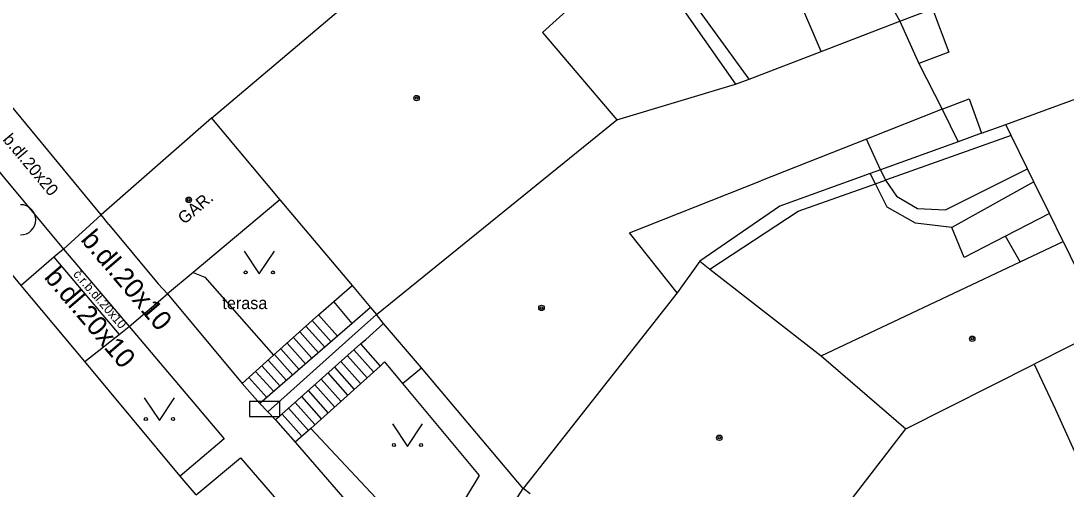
# Model space of a CAD drawing. Extents: x -595546 to -593986, y -1160845 to -1159202.
# Drawn here: x -595188.46 to -595153.91, y -1160596.94 to -1160581.47 of the extents above; entities that cross this region are included whole.
import ezdxf

# ---------------------------------------------------------------- set-up
doc = ezdxf.new("R2010")
doc.units = 0
for name, color, linetype in [('DOP - kresba z DSPS bez souradnic', 7, 'Continuous'), ('DOP - rozhrani ploch obecne', 7, 'Continuous'), ('Level 22', 7, 'Continuous'), ('Level 24', 7, 'Continuous'), ('Level 36', 7, 'Continuous'), ('Level 39', 7, 'Continuous'), ('TM - budovy zdene_ betonove - VP', 7, 'Continuous'), ('TM - chodniky - VP', 7, 'Continuous'), ('TM - komunikace - VP', 7, 'Continuous'), ('TM - letecke snimky - pomocna linie', 7, 'Continuous'), ('TM - podezdivka plotu - VP', 7, 'Continuous'), ('TM - popis objektu', 7, 'Continuous'), ('TM - popis povrchu', 7, 'Continuous'), ('TM - poznamka', 7, 'Continuous'), ('TM - rozhrani mezi zpev. plochami mezi sebou - VP', 7, 'Continuous'), ('TM - rozhrani ploch obecne - VP', 7, 'Continuous'), ('TM - schody - VP', 7, 'Continuous'), ('TM - vstup do budovy - zdene_ betonove', 7, 'Continuous'), ('TM - zed operna - VP', 7, 'Continuous')]:
    doc.layers.add(name, color=color, linetype=linetype)

msp = doc.modelspace()

# ---------------------------------------------------------------- linework, layer by layer
at = {"layer": 'DOP - kresba z DSPS bez souradnic'}
for points in [[(-595164.38, -1160583.39), (-595169.19, -1160576.78)], [(-595158, -1160584.39), (-595157.48, -1160585.46)], [(-595160.04, -1160586.39), (-595160.51, -1160585.38)], [(-595155.72, -1160585.26), (-595159.88, -1160586.73)], [(-595160.04, -1160586.39), (-595159.88, -1160586.73)], [(-595157.9, -1160587.71), (-595155.18, -1160586.36)], [(-595160.21, -1160586.85), (-595160.38, -1160586.51)], [(-595159.88, -1160586.73), (-595159.52, -1160587.26)], [(-595162.76, -1160587.75), (-595160.21, -1160586.85)], [(-595159.82, -1160587.62), (-595160.21, -1160586.85)], [(-595154.97, -1160586.79), (-595157.68, -1160588.29)], [(-595159.52, -1160587.26), (-595158.82, -1160587.67)], [(-595165.69, -1160589.67), (-595162.76, -1160587.75)], [(-595158.89, -1160588.15), (-595159.82, -1160587.62)], [(-595158.82, -1160587.67), (-595157.9, -1160587.71)], [(-595157.68, -1160588.29), (-595158.89, -1160588.15)], [(-595154.46, -1160587.83), (-595155.91, -1160588.58)], [(-595157.28, -1160589.29), (-595157.68, -1160588.29)], [(-595155.91, -1160588.58), (-595157.28, -1160589.29)], [(-595155.43, -1160589.43), (-595155.91, -1160588.58)]]:
    msp.add_lwpolyline(points, dxfattribs=at)
at = {"layer": 'DOP - rozhrani ploch obecne'}
for points in [[(-595169.65, -1160576.69), (-595164.84, -1160583.56)], [(-595159.4, -1160581.48), (-595158.33, -1160581.07)], [(-595158.33, -1160581.07), (-595157.78, -1160582.5)], [(-595157.78, -1160582.5), (-595158.78, -1160582.88)], [(-595155.9, -1160584.89), (-595152.8, -1160583.76)], [(-595158, -1160584.39), (-595157.11, -1160584.04)], [(-595157.11, -1160584.04), (-595156.7, -1160585.18)], [(-595156.7, -1160585.18), (-595155.9, -1160584.89)], [(-595155.72, -1160585.26), (-595155.9, -1160584.89)], [(-595156.7, -1160585.18), (-595157.48, -1160585.46)], [(-595155.18, -1160586.36), (-595155.72, -1160585.26)], [(-595157.48, -1160585.46), (-595160.04, -1160586.39)], [(-595160.04, -1160586.39), (-595160.38, -1160586.51)], [(-595154.97, -1160586.79), (-595155.18, -1160586.36)], [(-595160.38, -1160586.51), (-595163.37, -1160587.59)], [(-595154.46, -1160587.83), (-595154.97, -1160586.79)], [(-595163.37, -1160587.59), (-595166.02, -1160589.41)], [(-595154.01, -1160588.76), (-595154.46, -1160587.83)]]:
    msp.add_lwpolyline(points, dxfattribs=at)
at = {"layer": 'Level 22'}
msp.add_arc((-595188.47, -1160588.04), 0.5, 270, 90, dxfattribs=at)
at = {"layer": 'Level 24'}
msp.add_lwpolyline([(-595180.898, -1160594.539), (-595179.898, -1160594.539), (-595179.898, -1160594.039), (-595180.898, -1160594.039)], close=True, dxfattribs=at)
at = {"layer": 'Level 36'}
for points in [[(-595181.08, -1160589.08), (-595180.58, -1160589.83), (-595180.08, -1160589.08)], [(-595184.38, -1160593.92), (-595183.88, -1160594.67), (-595183.38, -1160593.92)], [(-595176.18, -1160594.78), (-595175.68, -1160595.53), (-595175.18, -1160594.78)]]:
    msp.add_lwpolyline(points, dxfattribs=at)
for centre in [(-595181.03, -1160589.78), (-595180.131, -1160589.78), (-595184.33, -1160594.62), (-595183.431, -1160594.62), (-595176.13, -1160595.48), (-595175.231, -1160595.48)]:
    msp.add_circle(centre, 0.05, dxfattribs=at)
at = {"layer": 'Level 39'}
for centre, radius in [((-595175.38, -1160584.02), 0.09), ((-595175.38, -1160584.02), 0.0398), ((-595182.91, -1160587.38), 0.09), ((-595182.91, -1160587.38), 0.0398), ((-595171.25, -1160590.95), 0.09), ((-595171.25, -1160590.95), 0.0398), ((-595157.01, -1160591.97), 0.09), ((-595157.01, -1160591.97), 0.0398), ((-595165.37, -1160595.24), 0.09), ((-595165.37, -1160595.24), 0.0398)]:
    msp.add_circle(centre, radius, dxfattribs=at)
at = {"layer": 'TM - budovy zdene_ betonove - VP'}
for points in [[(-595162, -1160582.48), (-595163.68, -1160578.57)], [(-595182.16, -1160584.68), (-595175.26, -1160578.85)], [(-595169.86, -1160580.62), (-595171.22, -1160581.85)], [(-595159.57, -1160581.18), (-595159.4, -1160581.48)], [(-595162, -1160582.48), (-595159.4, -1160581.48)], [(-595159.4, -1160581.48), (-595158.78, -1160582.88)], [(-595171.22, -1160581.85), (-595168.76, -1160584.74)], [(-595164.38, -1160583.39), (-595162, -1160582.48)], [(-595158.78, -1160582.88), (-595158, -1160584.39)], [(-595185.81, -1160587.88), (-595189.71, -1160583.16)], [(-595168.76, -1160584.74), (-595164.84, -1160583.56)], [(-595164.84, -1160583.56), (-595164.38, -1160583.39)], [(-595182.16, -1160584.68), (-595185.81, -1160587.88)], [(-595182.16, -1160584.68), (-595179.9, -1160587.38)], [(-595158, -1160584.39), (-595160.51, -1160585.38)], [(-595176.71, -1160591.17), (-595168.76, -1160584.74)], [(-595160.51, -1160585.38), (-595164, -1160586.75)], [(-595168.34, -1160588.47), (-595164, -1160586.75)], [(-595179.9, -1160587.38), (-595182.77, -1160589.78)], [(-595179.9, -1160587.38), (-595177.51, -1160590.21)], [(-595185.55, -1160588.2), (-595185.81, -1160587.88)], [(-595166.77, -1160590.45), (-595168.34, -1160588.47)], [(-595155.43, -1160589.43), (-595154.01, -1160588.76)], [(-595154.01, -1160588.76), (-595152.61, -1160591.62)], [(-595166.02, -1160589.41), (-595166.77, -1160590.45)], [(-595166.02, -1160589.41), (-595165.69, -1160589.67)], [(-595162, -1160592.53), (-595155.43, -1160589.43)], [(-595182.77, -1160589.78), (-595183.61, -1160590.48)], [(-595165.69, -1160589.67), (-595162, -1160592.53)], [(-595183.61, -1160590.48), (-595183.92, -1160590.16)], [(-595177.51, -1160590.21), (-595176.9, -1160590.94)], [(-595166.77, -1160590.45), (-595171.86, -1160596.92)], [(-595176.9, -1160590.94), (-595176.71, -1160591.17)], [(-595176.47, -1160591.46), (-595176.71, -1160591.17)], [(-595175.22, -1160592.93), (-595176.47, -1160591.46)], [(-595152.61, -1160591.62), (-595154.96, -1160592.81)], [(-595162, -1160592.53), (-595159.21, -1160594.95)], [(-595171.86, -1160596.92), (-595175.22, -1160592.93)], [(-595159.21, -1160594.95), (-595154.96, -1160592.81)], [(-595154.96, -1160592.81), (-595154.26, -1160594.31)], [(-595154.26, -1160594.31), (-595153.43, -1160596.13)], [(-595164.68, -1160602.05), (-595159.21, -1160594.95)], [(-595171.62, -1160597.09), (-595171.86, -1160596.92)]]:
    msp.add_lwpolyline(points, dxfattribs=at)
at = {"layer": 'TM - chodniky - VP'}
for points in [[(-595191.02, -1160584.25), (-595187.05, -1160589.01)], [(-595187.05, -1160589.01), (-595187.37, -1160589.27)], [(-595187.37, -1160589.27), (-595188.45, -1160590.21)], [(-595178.12, -1160590.74), (-595177.51, -1160590.21)], [(-595178.62, -1160591.18), (-595178.12, -1160590.74)], [(-595185.21, -1160591.83), (-595184.88, -1160591.56)], [(-595184.88, -1160591.56), (-595181.74, -1160595.28)], [(-595186.35, -1160592.72), (-595185.21, -1160591.83)], [(-595176.58, -1160592.87), (-595176.44, -1160592.73)], [(-595176.44, -1160592.73), (-595175.84, -1160593.45)], [(-595175.84, -1160593.45), (-595175.22, -1160592.93)], [(-595181.74, -1160595.28), (-595183.19, -1160596.51)], [(-595182.67, -1160597.12), (-595181.2, -1160595.9)], [(-595181.2, -1160595.9), (-595177.29, -1160600.43)]]:
    msp.add_lwpolyline(points, dxfattribs=at)
at = {"layer": 'TM - komunikace - VP'}
for points in [[(-595188.45, -1160590.21), (-595189.58, -1160588.86)], [(-595186.35, -1160592.72), (-595188.45, -1160590.21)], [(-595183.19, -1160596.51), (-595186.35, -1160592.72)], [(-595182.67, -1160597.12), (-595183.19, -1160596.51)]]:
    msp.add_lwpolyline(points, dxfattribs=at)
at = {"layer": 'TM - letecke snimky - pomocna linie'}
for points in [[(-595160.21, -1160586.85), (-595159.88, -1160586.73)], [(-595175.84, -1160593.45), (-595173.31, -1160596.49), (-595174.92, -1160599.15)]]:
    msp.add_lwpolyline(points, dxfattribs=at)
at = {"layer": 'TM - podezdivka plotu - VP'}
for points in [[(-595176.9, -1160590.94), (-595177.51, -1160591.46)], [(-595177.51, -1160591.46), (-595177.99, -1160591.88)], [(-595177.23, -1160592.14), (-595177.06, -1160591.99), (-595176.47, -1160591.46)], [(-595177.99, -1160591.88), (-595180.56, -1160594.11)], [(-595180.04, -1160594.65), (-595177.23, -1160592.14)], [(-595180.56, -1160594.11), (-595180.3, -1160594.38)], [(-595180.3, -1160594.38), (-595180.04, -1160594.65)]]:
    msp.add_lwpolyline(points, dxfattribs=at)
at = {"layer": 'TM - rozhrani mezi zpev. plochami mezi sebou - VP'}
for points in [[(-595185.81, -1160587.88), (-595187.05, -1160589.01)], [(-595187.05, -1160589.01), (-595184.88, -1160591.56)], [(-595187.37, -1160589.27), (-595185.21, -1160591.83)], [(-595184.88, -1160591.56), (-595183.61, -1160590.48)]]:
    msp.add_lwpolyline(points, dxfattribs=at)
at = {"layer": 'TM - rozhrani ploch obecne - VP'}
for points in [[(-595182.77, -1160589.78), (-595182.38, -1160589.93), (-595180.11, -1160592.51)], [(-595177.51, -1160591.46), (-595178.12, -1160590.74)], [(-595178.62, -1160591.18), (-595177.99, -1160591.88)], [(-595177.23, -1160592.14), (-595176.58, -1160592.87)], [(-595181.15, -1160593.45), (-595180.56, -1160594.11)], [(-595180.04, -1160594.65), (-595179.39, -1160595.38)], [(-595174.92, -1160599.15), (-595178.88, -1160594.93)], [(-595173.95, -1160600.18), (-595171.86, -1160596.92)]]:
    msp.add_lwpolyline(points, dxfattribs=at)
at = {"layer": 'TM - schody - VP'}
for points in [[(-595179.04, -1160591.55), (-595178.41, -1160592.25)], [(-595178.83, -1160591.37), (-595178.2, -1160592.07)], [(-595179.45, -1160591.93), (-595178.84, -1160592.61)], [(-595179.24, -1160591.74), (-595178.62, -1160592.43)], [(-595179.87, -1160592.3), (-595179.26, -1160592.98)], [(-595179.66, -1160592.11), (-595179.05, -1160592.8)], [(-595180.08, -1160592.49), (-595179.47, -1160593.17)], [(-595177.66, -1160592.53), (-595177.01, -1160593.26)], [(-595177.45, -1160592.33), (-595176.8, -1160593.06)], [(-595180.5, -1160592.86), (-595179.89, -1160593.53)], [(-595180.29, -1160592.68), (-595179.68, -1160593.35)], [(-595178.09, -1160592.91), (-595177.44, -1160593.64)], [(-595177.88, -1160592.72), (-595177.23, -1160593.45)], [(-595180.93, -1160593.25), (-595180.33, -1160593.91)], [(-595180.7, -1160593.05), (-595180.1, -1160593.71)], [(-595178.53, -1160593.3), (-595177.88, -1160594.03)], [(-595178.31, -1160593.1), (-595177.66, -1160593.83)], [(-595178.96, -1160593.68), (-595178.31, -1160594.42)], [(-595178.74, -1160593.49), (-595178.09, -1160594.22)], [(-595179.18, -1160593.88), (-595178.53, -1160594.61)], [(-595179.61, -1160594.26), (-595178.95, -1160595)], [(-595179.39, -1160594.07), (-595178.74, -1160594.8)], [(-595179.82, -1160594.46), (-595179.17, -1160595.19)]]:
    msp.add_lwpolyline(points, dxfattribs=at)
at = {"layer": 'TM - vstup do budovy - zdene_ betonove'}
msp.add_lwpolyline([(-595185.55, -1160588.2), (-595183.92, -1160590.16)], dxfattribs=at)
at = {"layer": 'TM - zed operna - VP'}
for points in [[(-595183.61, -1160590.48), (-595181.15, -1160593.45)], [(-595180.11, -1160592.51), (-595178.62, -1160591.18)], [(-595177.3, -1160591.7), (-595176.71, -1160591.17)], [(-595180.3, -1160594.38), (-595177.3, -1160591.7)], [(-595181.15, -1160593.45), (-595180.11, -1160592.51)], [(-595176.58, -1160592.87), (-595178.88, -1160594.93)], [(-595178.88, -1160594.93), (-595179.39, -1160595.38)], [(-595179.39, -1160595.38), (-595174.76, -1160600.73)]]:
    msp.add_lwpolyline(points, dxfattribs=at)

# ---------------------------------------------------------------- texts
at = {"layer": 'TM - popis objektu'}
msp.add_text('GAR.', height=0.4, rotation=40.3509, dxfattribs=at).set_placement((-595183.06, -1160588.21))
at = {"layer": 'TM - popis povrchu'}
for s, height, rotation, p in [('b.dl.20x20', 0.4, 310, (-595189.08, -1160585.4)), ('b.dl.20x10', 0.65, 310.5111, (-595186.51, -1160588.71)), ('b.dl.20x10', 0.65, 310.5111, (-595187.72, -1160589.95)), ('č.r.b.dl.20x10', 0.3, 311.0055, (-595186.75, -1160589.85))]:
    msp.add_text(s, height=height, rotation=rotation, dxfattribs=at).set_placement(p)
at = {"layer": 'TM - poznamka'}
msp.add_text('terasa', height=0.4, dxfattribs=at).set_placement((-595181.8, -1160590.99))

doc.saveas('drawing.dxf')
